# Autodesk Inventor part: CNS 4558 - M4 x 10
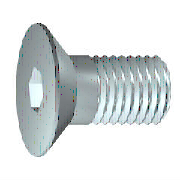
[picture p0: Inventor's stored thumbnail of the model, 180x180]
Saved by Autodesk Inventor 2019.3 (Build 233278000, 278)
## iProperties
Created: 2018-01
Part Number: CNS 4558 - M4 x 10
Material: Ocel, měkká
Description: Šroub se zápustnou hlavou
Document SubType Name: Modeling
Standard: CNS 4558
Designer: B-hon
Standards Organization: CNS
Language: cs-CZ
Size Designation: M4 x 10
Categories: <MemberInstance><Categories><Category DisplayName="Spojovací materiál" InternalName="e4da775c-781d-43d5-af7c-5136215cf5a6" Mnemonic="FSTN"><Category DisplayName
Density: 7.85 g/cm^3
Appearance: Pololeštěná
IsCustomPart: 0
Author: B-hon
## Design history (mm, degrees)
body "Solid1"
revolve "Těleso" stored, may be unused: angle "d13" = 90 deg
sketch "Náčrt2"
  geometry: L1 (0, -5.6)-(0, 5.6) reference; L2 (-5.6, 0)-(5.6, 0) reference; L3 (1.443, 0)-(0.722, -1.25); L4 (0.722, -1.25)-(-0.722, -1.25); L5 (-0.722, -1.25)-(-1.443, 0); L6 (-1.443, 0)-(-0.722, 1.25); L7 (-0.722, 1.25)-(0.722, 1.25); L8 (0.722, 1.25)-(1.443, 0); A1 r 1.443 centre (0, 0) between (0, 1.443) and (1.443, 0) reference; 2 further points
  constraints: 12 end point, 2 coincident, 2 point on circle, 2 point on line, 12 other
extrude "Drážka" join sketch "Náčrt2" taper "d14" = 0 deg; stored distance "d30" = 10
feature "Závit" dims "d15" = 5.6 (= GEL), "d16" = 0
chamfer "Zkosení1" distance "d17" = 0.42941 (= -0.5 x SPD + 0.5 x GD); stored, may be unused: second distance "d18" = 0.42941 (= GUL), angle "d39" = 45 deg
workplane "Work Plane1"
sketch "Náčrt1"
  geometry: L1 (10, 0)-(10, 2); L2 (10, 2)-(4.4, 2); L3 (4.4, 2)-(3.971, 2); L4 (0, 4)-(0, 1.443); L5 (0, 1.443)-(1.8, 1.443); L6 (1.8, 1.443)-(2.633, 0); L7 (2.633, 0)-(10, 0); L8 (0, 4)-(0.3, 4); L9 (0.3, 4)-(2.3, 2); L10 (3.971, 2)-(2.3, 2); L11 (4.4, 2)-(2.3, 2); L12 (2.3, 2)-(2.3, 2); L13 (-2, 0)-(12, 0) reference; L14 (0, -0.8)-(0, 4.8) reference
  constraints: 24 end point, 4 collinear, 3 parallel
  dimensions: "d0" = 10 distance between parallel lines of L4 L1 (= NLG); "d1" = 5.6 distance from line of L2.end L1 (= GEL); "d2" = 1.8 distance from line of L5.end L4 (= INTI); "d3" = 4 diameter of L2 L7 (= GD); "d6" = 2.3 distance from line of L9.end L4 (= KOH); "d7" = 45 deg angle of L9 L7 (= 0.5 x SEWI); "d8" = 2.88675 diameter of L5 L7 (= 1.1547 x SW); "d9" = 60 deg angle of L6 L7; "d10" = 8 diameter of L8 L7 (= KOD); "d11" = 4 diameter of L10 L7 (= BDM); "d12" = 0.42941 distance of L3.end L2.end (= GAL)
other parameters: "NLG" = 10 [user parameter; used in 1 equation term], "INTI" = 1.8 [user parameter; used in 1 equation term], "GEL" = 5.6 [user parameter; used in 2 equation terms], "GAL" = 0.42941 (= 0.61345 x PTC) [user parameter; used in 1 equation term], "KOH" = 2.3 [user parameter; used in 1 equation term], "KOD" = 8 [user parameter; used in 1 equation term], "GUL" = 0.42941 (= 0.61345 x PTC) [user parameter; used in 1 equation term], "SPD" = 3.14117 (= NND - 1.2269 x PTC) [user parameter; used in 1 equation term], "BDM" = 4 (= NND) [user parameter; used in 1 equation term], "GD" = 4 (= NND) [user parameter; used in 2 equation terms], "SEWI" = 90 deg [user parameter; used in 1 equation term], "d20" = 0, "SW" = 2.5 [user parameter; used in 2 equation terms], "d43" = 0, "d44" = 0, "TOA" = 30 deg [user parameter], "GD1" = 3.14117 (= THREADDIA - 1.2269 x PTC) [user parameter], "EPV" = 4.3 [user parameter], "THREADDIA" = 4 [user parameter; used in 1 equation term], "TPU" = 14.28571 (computed from PTC) [user parameter], "PTC" = 0.7 [user parameter; used in 5 equation terms], "NND" = 4 [user parameter; used in 3 equation terms], "E0" = 2.8875 (= 1.155 x SW) [user parameter]
